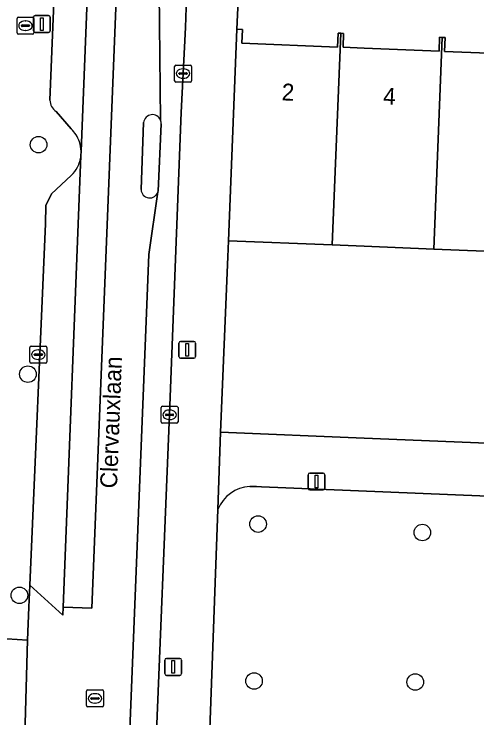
# Model space of a CAD drawing. Extents: x 160786 to 161429, y 386828 to 387485.
# Drawn here: x 160979.3 to 161006.66, y 386923.3 to 386964.94 of the extents above; entities that cross this region are included whole.
import ezdxf

# ---------------------------------------------------------------- set-up
doc = ezdxf.new("R2010")
doc.units = 0
for name, color, linetype in [('IMGEO_Boom', 7, 'Continuous'), ('IMGEO_Brandkraan', 7, 'Continuous'), ('IMGEO_Erf', 7, 'Continuous'), ('IMGEO_Groenvoorziening', 7, 'Continuous'), ('IMGEO_Kolk', 7, 'Continuous'), ('IMGEO_Lichtmast', 7, 'Continuous'), ('IMGEO_Muur', 7, 'Continuous'), ('IMGEO_Openbare_ruimte_label', 7, 'Continuous'), ('IMGEO_Pand', 7, 'Continuous'), ('IMGEO_Pand_nummerreeks', 7, 'Continuous'), ('IMGEO_Parkeervlak_gesloten', 7, 'Continuous'), ('IMGEO_Rijbaan_lokaal_gesloten', 7, 'Continuous'), ('IMGEO_Rijbaan_lokaal_open', 7, 'Continuous'), ('IMGEO_Rioolput', 7, 'Continuous'), ('IMGEO_Verkeerseiland_gesloten', 7, 'Continuous'), ('IMGEO_Voetpad_open', 7, 'Continuous')]:
    doc.layers.add(name, color=color, linetype=linetype)

msp = doc.modelspace()

# ---------------------------------------------------------------- linework, layer by layer
at = {"layer": 'IMGEO_Boom'}
for centre in [(160980.747, 386957.214), (160980.116, 386943.638), (160993.724, 386934.769), (161003.435, 386934.27), (160979.614, 386930.557), (160993.485, 386925.485), (161003.015, 386925.424)]:
    msp.add_circle(centre, 0.489, dxfattribs=at)
at = {"layer": 'IMGEO_Brandkraan'}
for p, q in [((160979.472, 386963.826), (160979.472, 386964.678)), ((160979.547, 386964.752), (160980.399, 386964.752)), ((160979.96, 386964.532), (160979.985, 386964.532)), ((160980.473, 386964.678), (160980.473, 386963.826)), ((160979.731, 386964.246), (160979.731, 386964.258)), ((160980.169, 386964.209), (160979.771, 386964.209)), ((160979.774, 386964.295), (160980.172, 386964.295)), ((160979.983, 386963.972), (160979.958, 386963.972)), ((160980.215, 386964.258), (160980.215, 386964.246)), ((160980.399, 386963.752), (160979.547, 386963.752))]:
    msp.add_line(p, q, dxfattribs=at)
for points in [[(160979.472, 386963.826), (160979.472, 386964.678)], [(160979.547, 386964.752), (160980.399, 386964.752)], [(160980.473, 386964.678), (160980.473, 386963.826)], [(160980.399, 386963.752), (160979.547, 386963.752)]]:
    msp.add_lwpolyline(points, dxfattribs=at)
for centre, radius, start, end in [((160979.549, 386964.676), 0.0765, 91.552, 178.448), ((160979.549, 386964.676), 0.0765, 91.552, 178.448), ((160980.397, 386964.676), 0.0765, 1.552, 88.448), ((160980.397, 386964.676), 0.0765, 1.552, 88.448), ((160979.771, 386964.255), 0.0403, 85.8775, 175.7526), ((160979.768, 386964.245), 0.0366, 178.938, 274.7102), ((160980.172, 386964.252), 0.043, 264.8664, 352.4533), ((160980.176, 386964.257), 0.0386, 1.7309, 96.639), ((160979.549, 386963.828), 0.0765, 181.552, 268.448), ((160979.549, 386963.828), 0.0765, 181.552, 268.448), ((160980.397, 386963.828), 0.0765, 271.552, 358.448), ((160980.397, 386963.828), 0.0765, 271.552, 358.448)]:
    msp.add_arc(centre, radius, start, end, dxfattribs=at)
for centre, major_axis, ratio, start_param, end_param in [((160979.959, 386964.252), (-0.387, 0.002), 0.722429, 4.712389, 7.853982), ((160979.984, 386964.252), (-0.39, 0.002), 0.717154, 1.570796, 4.712389)]:
    msp.add_ellipse(centre, major_axis=major_axis, ratio=ratio, start_param=start_param, end_param=end_param, dxfattribs=at)
at = {"layer": 'IMGEO_Erf'}
msp.add_lwpolyline([(161033.803, 386940.315), (161034.227, 386948.864), (161034.266, 386949.814), (161028.105, 386950.064), (161022.105, 386950.308), (161016.105, 386950.552), (161010.106, 386950.796), (161004.105, 386951.04), (161000, 386951.207), (160998.105, 386951.284), (160991.968, 386951.533), (160991.929, 386950.583), (160991.5, 386940.197), (161000, 386939.854), (161031.883, 386938.55)], dxfattribs=at)
at = {"layer": 'IMGEO_Groenvoorziening'}
for points in [[(161033.104, 386927.737), (161012.25, 386928.575), (161012.565, 386936.195), (160993.932, 386936.966), (160993.624, 386936.993), (160993.229, 386936.995)], [(160991.347, 386935.625), (160990.649, 386916.69)]]:
    msp.add_lwpolyline(points, dxfattribs=at)
msp.add_arc((160993.352, 386934.848), 2.151, 93.2892, 158.8162, dxfattribs=at)
at = {"layer": 'IMGEO_Kolk'}
for p, q in [((160988.864, 386961.92), (160989.716, 386961.92)), ((160988.789, 386960.994), (160988.789, 386961.846)), ((160989.091, 386961.463), (160989.489, 386961.463)), ((160989.277, 386961.7), (160989.302, 386961.7)), ((160989.79, 386961.846), (160989.79, 386960.994)), ((160989.048, 386961.414), (160989.048, 386961.426)), ((160989.486, 386961.377), (160989.088, 386961.377)), ((160989.3, 386961.14), (160989.275, 386961.14)), ((160989.532, 386961.426), (160989.532, 386961.414)), ((160989.716, 386960.92), (160988.864, 386960.92)), ((160980.234, 386944.365), (160980.234, 386945.217)), ((160980.309, 386945.291), (160981.161, 386945.291)), ((160981.235, 386945.217), (160981.235, 386944.365)), ((160980.493, 386944.785), (160980.493, 386944.797)), ((160980.536, 386944.834), (160980.934, 386944.834)), ((160980.722, 386945.071), (160980.747, 386945.071)), ((160980.977, 386944.797), (160980.977, 386944.785)), ((160980.931, 386944.748), (160980.533, 386944.748)), ((160980.745, 386944.511), (160980.72, 386944.511)), ((160981.161, 386944.291), (160980.309, 386944.291)), ((160987.99, 386940.81), (160987.99, 386941.662)), ((160988.065, 386941.736), (160988.917, 386941.736)), ((160988.478, 386941.516), (160988.503, 386941.516)), ((160988.991, 386941.662), (160988.991, 386940.81)), ((160988.249, 386941.23), (160988.249, 386941.242)), ((160988.687, 386941.193), (160988.289, 386941.193)), ((160988.292, 386941.279), (160988.69, 386941.279)), ((160988.733, 386941.242), (160988.733, 386941.23)), ((160988.917, 386940.736), (160988.065, 386940.736)), ((160988.501, 386940.956), (160988.476, 386940.956))]:
    msp.add_line(p, q, dxfattribs=at)
for points in [[(160988.864, 386961.92), (160989.716, 386961.92)], [(160988.789, 386960.994), (160988.789, 386961.846)], [(160989.79, 386961.846), (160989.79, 386960.994)], [(160989.716, 386960.92), (160988.864, 386960.92)], [(160980.234, 386944.365), (160980.234, 386945.217)], [(160980.309, 386945.291), (160981.161, 386945.291)], [(160981.235, 386945.217), (160981.235, 386944.365)], [(160981.161, 386944.291), (160980.309, 386944.291)], [(160987.99, 386940.81), (160987.99, 386941.662)], [(160988.065, 386941.736), (160988.917, 386941.736)], [(160988.991, 386941.662), (160988.991, 386940.81)], [(160988.917, 386940.736), (160988.065, 386940.736)]]:
    msp.add_lwpolyline(points, dxfattribs=at)
for centre, radius, start, end in [((160988.866, 386961.844), 0.0765, 91.552, 178.448), ((160988.866, 386961.844), 0.0765, 91.552, 178.448), ((160989.714, 386961.844), 0.0765, 1.552, 88.448), ((160989.714, 386961.844), 0.0765, 1.552, 88.448), ((160989.088, 386961.423), 0.0403, 85.8775, 175.7526), ((160989.493, 386961.425), 0.0386, 1.7309, 96.639), ((160989.085, 386961.413), 0.0366, 178.938, 274.7102), ((160989.489, 386961.42), 0.043, 264.8664, 352.4533), ((160988.866, 386960.996), 0.0765, 181.552, 268.448), ((160988.866, 386960.996), 0.0765, 181.552, 268.448), ((160989.714, 386960.996), 0.0765, 271.552, 358.448), ((160989.714, 386960.996), 0.0765, 271.552, 358.448), ((160980.311, 386945.215), 0.0765, 91.552, 178.448), ((160980.311, 386945.215), 0.0765, 91.552, 178.448), ((160981.159, 386945.215), 0.0765, 1.552, 88.448), ((160981.159, 386945.215), 0.0765, 1.552, 88.448), ((160980.533, 386944.794), 0.0403, 85.8775, 175.7526), ((160980.53, 386944.784), 0.0366, 178.938, 274.7102), ((160980.934, 386944.791), 0.043, 264.8664, 352.4533), ((160980.938, 386944.796), 0.0386, 1.7309, 96.639), ((160980.311, 386944.367), 0.0765, 181.552, 268.448), ((160980.311, 386944.367), 0.0765, 181.552, 268.448), ((160981.159, 386944.367), 0.0765, 271.552, 358.448), ((160981.159, 386944.367), 0.0765, 271.552, 358.448), ((160988.067, 386941.66), 0.0765, 91.552, 178.448), ((160988.067, 386941.66), 0.0765, 91.552, 178.448), ((160988.915, 386941.66), 0.0765, 1.552, 88.448), ((160988.915, 386941.66), 0.0765, 1.552, 88.448), ((160988.289, 386941.239), 0.0403, 85.8775, 175.7526), ((160988.286, 386941.229), 0.0366, 178.938, 274.7102), ((160988.69, 386941.236), 0.043, 264.8664, 352.4533), ((160988.694, 386941.241), 0.0386, 1.7309, 96.639), ((160988.067, 386940.812), 0.0765, 181.552, 268.448), ((160988.067, 386940.812), 0.0765, 181.552, 268.448), ((160988.915, 386940.812), 0.0765, 271.552, 358.448), ((160988.915, 386940.812), 0.0765, 271.552, 358.448)]:
    msp.add_arc(centre, radius, start, end, dxfattribs=at)
for centre, major_axis, ratio, start_param, end_param in [((160989.276, 386961.42), (-0.387, 0.002), 0.722429, 4.712389, 7.853982), ((160989.301, 386961.42), (-0.39, 0.002), 0.717154, 1.570796, 4.712389), ((160980.721, 386944.791), (-0.387, 0.002), 0.722429, 4.712389, 7.853982), ((160980.746, 386944.791), (-0.39, 0.002), 0.717154, 1.570796, 4.712389), ((160988.477, 386941.236), (-0.387, 0.002), 0.722429, 4.712389, 7.853982), ((160988.502, 386941.236), (-0.39, 0.002), 0.717154, 1.570796, 4.712389)]:
    msp.add_ellipse(centre, major_axis=major_axis, ratio=ratio, start_param=start_param, end_param=end_param, dxfattribs=at)
at = {"layer": 'IMGEO_Lichtmast'}
for p, q in [((160980.543, 386964.851), (160981.333, 386964.851)), ((160981.333, 386964.851), (160980.543, 386964.851)), ((160980.443, 386963.951), (160980.443, 386964.751)), ((160980.443, 386964.751), (160980.443, 386963.951)), ((160981.433, 386964.751), (160981.433, 386963.951)), ((160981.433, 386963.951), (160981.433, 386964.751)), ((160981.333, 386963.851), (160980.543, 386963.851)), ((160980.543, 386963.851), (160981.333, 386963.851)), ((160989.041, 386944.679), (160989.041, 386945.479)), ((160989.041, 386945.479), (160989.041, 386944.679)), ((160989.141, 386945.579), (160989.931, 386945.579)), ((160989.931, 386945.579), (160989.141, 386945.579)), ((160990.031, 386945.479), (160990.031, 386944.679)), ((160990.031, 386944.679), (160990.031, 386945.479)), ((160989.931, 386944.579), (160989.141, 386944.579)), ((160989.141, 386944.579), (160989.931, 386944.579)), ((160996.777, 386937.79), (160997.567, 386937.79)), ((160997.567, 386937.79), (160996.777, 386937.79)), ((160996.677, 386936.89), (160996.677, 386937.69)), ((160996.677, 386937.69), (160996.677, 386936.89)), ((160997.667, 386937.69), (160997.667, 386936.89)), ((160997.667, 386936.89), (160997.667, 386937.69)), ((160997.567, 386936.79), (160996.777, 386936.79)), ((160996.777, 386936.79), (160997.567, 386936.79)), ((160988.208, 386925.921), (160988.208, 386926.721)), ((160988.208, 386926.721), (160988.208, 386925.921)), ((160988.308, 386926.821), (160989.098, 386926.821)), ((160989.098, 386926.821), (160988.308, 386926.821)), ((160989.198, 386926.721), (160989.198, 386925.921)), ((160989.198, 386925.921), (160989.198, 386926.721)), ((160989.098, 386925.821), (160988.308, 386925.821)), ((160988.308, 386925.821), (160989.098, 386925.821))]:
    msp.add_line(p, q, dxfattribs=at)
for points in [[(160980.863, 386964.726), (160981.013, 386964.726), (160981.013, 386963.976), (160980.863, 386963.976), (160980.863, 386964.726)], [(160989.461, 386945.454), (160989.611, 386945.454), (160989.611, 386944.704), (160989.461, 386944.704), (160989.461, 386945.454)], [(160997.097, 386937.665), (160997.247, 386937.665), (160997.247, 386936.915), (160997.097, 386936.915), (160997.097, 386937.665)], [(160988.628, 386926.696), (160988.778, 386926.696), (160988.778, 386925.946), (160988.628, 386925.946), (160988.628, 386926.696)]]:
    msp.add_lwpolyline(points, dxfattribs=at)
for centre, start, end in [((160980.543, 386964.751), 90, 180), ((160980.543, 386964.751), 90, 180), ((160981.333, 386964.751), 0, 90), ((160981.333, 386964.751), 360, 90), ((160980.543, 386963.951), 180, 270), ((160980.543, 386963.951), 180, 270), ((160981.333, 386963.951), 270, 0), ((160981.333, 386963.951), 270, 0), ((160989.141, 386945.479), 90, 180), ((160989.141, 386945.479), 90, 180), ((160989.931, 386945.479), 0, 90), ((160989.931, 386945.479), 360, 90), ((160989.141, 386944.679), 180, 270), ((160989.141, 386944.679), 180, 270), ((160989.931, 386944.679), 270, 0), ((160989.931, 386944.679), 270, 0), ((160996.777, 386937.69), 90, 180), ((160996.777, 386937.69), 90, 180), ((160997.567, 386937.69), 0, 90), ((160997.567, 386937.69), 360, 90), ((160996.777, 386936.89), 180, 270), ((160996.777, 386936.89), 180, 270), ((160997.567, 386936.89), 270, 0), ((160997.567, 386936.89), 270, 0), ((160988.308, 386926.721), 90, 180), ((160988.308, 386926.721), 90, 180), ((160989.098, 386926.721), 0, 90), ((160989.098, 386926.721), 360, 90), ((160988.308, 386925.921), 180, 270), ((160988.308, 386925.921), 180, 270), ((160989.098, 386925.921), 270, 0), ((160989.098, 386925.921), 270, 0)]:
    msp.add_arc(centre, 0.1, start, end, dxfattribs=at)
at = {"layer": 'IMGEO_Muur'}
for points in [[(160991.968, 386951.533), (160991.929, 386950.583)], [(160991.929, 386950.583), (160991.5, 386940.197)]]:
    msp.add_lwpolyline(points, dxfattribs=at)
at = {"layer": 'IMGEO_Pand'}
for points in [[(160998.457, 386963.811), (160998.424, 386962.985), (160992.763, 386963.215), (160992.796, 386964.034), (160992.476, 386964.047), (160991.968, 386951.533), (160998.105, 386951.284), (160998.615, 386963.805)], [(161004.457, 386963.567), (161004.424, 386962.748), (161000, 386962.928), (160998.744, 386962.979), (160998.777, 386963.798), (160998.615, 386963.805), (160998.105, 386951.284), (161000, 386951.207), (161004.105, 386951.04), (161004.615, 386963.561)], [(161010.457, 386963.323), (161010.424, 386962.504), (161004.744, 386962.735), (161004.777, 386963.554), (161004.615, 386963.561), (161004.105, 386951.04), (161010.106, 386950.796), (161010.615, 386963.316)]]:
    msp.add_lwpolyline(points, close=True, dxfattribs=at)
at = {"layer": 'IMGEO_Parkeervlak_gesloten'}
for points in [[(160984.531, 386988.762), (160982.59, 386988.817), (160981.419, 386959.85)], [(160983.262, 386956.829), (160984.531, 386988.762)], [(160981.781, 386959.176), (160982.672, 386958.148)], [(160982.678, 386955.399), (160981.517, 386954.306), (160981.17, 386953.623), (160981.158, 386952.537), (160980.231, 386931.159), (160982.189, 386929.378), (160982.208, 386929.85), (160983.251, 386956.562)]]:
    msp.add_lwpolyline(points, dxfattribs=at)
for centre, radius, start, end in [((160982.252, 386959.863), 0.833, 180.8942, 235.5856), ((160981.348, 386956.761), 1.917, 18.7919, 46.3239), ((160981.383, 386956.775), 1.88, 1.6551, 18.7529), ((160981.365, 386956.769), 1.897, 332.3721, 353.7458), ((160981.371, 386956.764), 1.89, 313.7635, 332.4219)]:
    msp.add_arc(centre, radius, start, end, dxfattribs=at)
at = {"layer": 'IMGEO_Rijbaan_lokaal_gesloten'}
for points in [[(160987.959, 386958.658), (160987.876, 386966.266), (160992.785, 387087.527), (160990.199, 387087.638), (160983.902, 386929.785), (160982.208, 386929.85), (160982.189, 386929.378), (160980.231, 386931.159), (160980.175, 386929.863), (160980.09, 386927.898), (160979.942, 386922.265), (160979.941, 386922.229), (160981.745, 386922.17)], [(160984.712, 386993.626), (160984.531, 386988.762), (160983.262, 386956.829), (160983.251, 386956.562), (160982.208, 386929.85), (160983.902, 386929.785), (160990.199, 387087.638)], [(160992.274, 387030.665), (160992.337, 387032.289), (160992.597, 387038.997), (160993.259, 387056.065), (160994.21, 387079.435), (160994.515, 387085.035), (160994.612, 387087.501), (160992.785, 387087.527), (160987.876, 386966.266), (160987.959, 386958.658)], [(160987.64, 386919.555), (160987.637, 386920.517), (160988.491, 386941.272), (160989.174, 386959.126), (160989.425, 386964.144), (160989.53, 386967.133), (160989.72, 386972.632), (160989.974, 386978.34), (160990.002, 386979.005), (160990.152, 386982.628), (160990.167, 386982.998), (160990.497, 386990.405), (160990.992, 387000), (160991.155, 387003.893), (160991.434, 387010.584), (160992.274, 387030.665)], [(160987.992, 386958.443), (160987.814, 386954.469), (160987.805, 386954.433), (160987.273, 386950.712), (160986.053, 386920.644)], [(160986.805, 386954.556), (160986.957, 386958.522)], [(160986.053, 386920.644), (160987.273, 386950.712), (160987.805, 386954.433)]]:
    msp.add_lwpolyline(points, dxfattribs=at)
for centre, radius, start, end in [((160987.474, 386958.473), 0.519, 20.8346, 174.6243), ((160987.477, 386958.474), 0.516, 356.5558, 20.8965), ((160987.314, 386954.57), 0.509, 181.5273, 344.4484)]:
    msp.add_arc(centre, radius, start, end, dxfattribs=at)
at = {"layer": 'IMGEO_Rijbaan_lokaal_open'}
for points in [[(160992.599, 386967.047), (160992.476, 386964.047), (160992.796, 386964.034), (160992.763, 386963.215), (160998.424, 386962.985), (160998.457, 386963.811), (160998.615, 386963.805), (160998.777, 386963.798), (160998.744, 386962.979), (161000, 386962.928), (161004.424, 386962.748), (161004.457, 386963.567), (161004.615, 386963.561), (161004.777, 386963.554), (161004.744, 386962.735), (161010.424, 386962.504), (161010.457, 386963.323), (161010.615, 386963.316), (161010.776, 386963.309), (161010.743, 386962.49), (161016.203, 386962.268), (161016.581, 386971.618)], [(160950.247, 386936.098), (160950.494, 386941.959), (160947.593, 386942.07), (160909.763, 386943.521), (160909.024, 386925.361), (160908.899, 386922.288), (160924.183, 386921.716), (160939.56, 386921.141), (160942.121, 386921.036), (160965.405, 386920.165), (160967.922, 386920.071), (160968.031, 386922.765), (160970.467, 386922.647), (160978.3, 386922.336), (160979.942, 386922.265), (160980.09, 386927.898), (160977.011, 386928.093), (160956.943, 386928.854)]]:
    msp.add_lwpolyline(points, dxfattribs=at)
at = {"layer": 'IMGEO_Rioolput'}
for p, q in [((160983.578, 386924.031), (160983.578, 386924.883)), ((160983.653, 386924.957), (160984.505, 386924.957)), ((160984.579, 386924.883), (160984.579, 386924.031)), ((160983.837, 386924.451), (160983.837, 386924.463)), ((160984.275, 386924.414), (160983.877, 386924.414)), ((160983.88, 386924.5), (160984.278, 386924.5)), ((160984.066, 386924.737), (160984.091, 386924.737)), ((160984.321, 386924.463), (160984.321, 386924.451)), ((160984.089, 386924.177), (160984.064, 386924.177)), ((160984.505, 386923.957), (160983.653, 386923.957))]:
    msp.add_line(p, q, dxfattribs=at)
for points in [[(160983.578, 386924.031), (160983.578, 386924.883)], [(160983.653, 386924.957), (160984.505, 386924.957)], [(160984.579, 386924.883), (160984.579, 386924.031)], [(160984.505, 386923.957), (160983.653, 386923.957)]]:
    msp.add_lwpolyline(points, dxfattribs=at)
for centre, radius, start, end in [((160983.655, 386924.881), 0.0765, 91.552, 178.448), ((160983.655, 386924.881), 0.0765, 91.552, 178.448), ((160984.503, 386924.881), 0.0765, 1.552, 88.448), ((160984.503, 386924.881), 0.0765, 1.552, 88.448), ((160983.877, 386924.46), 0.0403, 85.8775, 175.7526), ((160983.874, 386924.45), 0.0366, 178.938, 274.7102), ((160984.278, 386924.457), 0.043, 264.8664, 352.4533), ((160984.282, 386924.462), 0.0386, 1.7309, 96.639), ((160983.655, 386924.033), 0.0765, 181.552, 268.448), ((160983.655, 386924.033), 0.0765, 181.552, 268.448), ((160984.503, 386924.033), 0.0765, 271.552, 358.448), ((160984.503, 386924.033), 0.0765, 271.552, 358.448)]:
    msp.add_arc(centre, radius, start, end, dxfattribs=at)
for centre, major_axis, ratio, start_param, end_param in [((160984.065, 386924.457), (-0.387, 0.002), 0.722429, 4.712389, 7.853982), ((160984.09, 386924.457), (-0.39, 0.002), 0.717154, 1.570796, 4.712389)]:
    msp.add_ellipse(centre, major_axis=major_axis, ratio=ratio, start_param=start_param, end_param=end_param, dxfattribs=at)
at = {"layer": 'IMGEO_Verkeerseiland_gesloten'}
for points in [[(160986.957, 386958.522), (160986.805, 386954.556)], [(160987.805, 386954.433), (160987.814, 386954.469), (160987.992, 386958.443)]]:
    msp.add_lwpolyline(points, dxfattribs=at)
for centre, radius, start, end in [((160987.474, 386958.473), 0.519, 20.8346, 174.6243), ((160987.477, 386958.474), 0.516, 356.5558, 20.8965), ((160987.314, 386954.57), 0.509, 181.5273, 344.4484)]:
    msp.add_arc(centre, radius, start, end, dxfattribs=at)
at = {"layer": 'IMGEO_Voetpad_open'}
for points in [[(160981.419, 386959.85), (160982.59, 386988.817), (160982.679, 386991.028), (160983.018, 386991.698), (160984.269, 386992.759)], [(160977.018, 386992.268), (160976.973, 386989.708), (160979.245, 386983.695), (160979.111, 386978.996), (160979.035, 386977.005), (160978.96, 386975.016), (160978.59, 386965.715), (160978.516, 386963.768), (160978.441, 386961.82), (160978.026, 386952.65), (160977.951, 386950.68), (160977.876, 386948.712), (160977.497, 386939.446), (160977.422, 386937.468), (160977.347, 386935.491), (160977.011, 386928.093), (160980.09, 386927.898), (160980.175, 386929.863), (160980.231, 386931.159), (160981.158, 386952.537), (160981.17, 386953.623), (160981.517, 386954.306), (160982.678, 386955.399)], [(160991.347, 386935.625), (160991.5, 386940.197), (160991.929, 386950.583), (160991.968, 386951.533), (160992.476, 386964.047), (160992.599, 386967.047), (160989.53, 386967.133), (160989.425, 386964.144), (160989.174, 386959.126), (160988.491, 386941.272), (160987.637, 386920.517), (160987.64, 386919.555)], [(160982.672, 386958.148), (160981.781, 386959.176)], [(160983.251, 386956.562), (160983.262, 386956.829)], [(161090.255, 386936.31), (161090.15, 386936.295), (161082.967, 386936.595), (161082.88, 386936.613), (161038.862, 386938.273), (161038.808, 386938.265), (161031.942, 386938.539), (161031.883, 386938.55), (161000, 386939.854), (160991.5, 386940.197), (160991.347, 386935.625)], [(160993.229, 386936.995), (160993.624, 386936.993), (160993.932, 386936.966), (161012.565, 386936.195), (161031.411, 386935.415), (161031.656, 386935.361), (161031.901, 386935.303), (161032.069, 386935.257), (161032.386, 386935.15)], [(160989.719, 386913.07), (160990.649, 386916.69), (160991.347, 386935.625)]]:
    msp.add_lwpolyline(points, dxfattribs=at)
for centre, radius, start, end in [((160982.252, 386959.863), 0.833, 180.8942, 235.5856), ((160981.348, 386956.761), 1.917, 18.7919, 46.3239), ((160981.383, 386956.775), 1.88, 1.6551, 18.7529), ((160981.365, 386956.769), 1.897, 332.3721, 353.7458), ((160981.371, 386956.764), 1.89, 313.7635, 332.4219), ((160993.352, 386934.848), 2.151, 93.2892, 158.8162)]:
    msp.add_arc(centre, radius, start, end, dxfattribs=at)

# ---------------------------------------------------------------- texts
at = {"layer": 'IMGEO_Openbare_ruimte_label'}
msp.add_text('Clervauxlaan', height=1, rotation=87.8216, dxfattribs=at).set_placement((160985.38, 386936.869))
at = {"layer": 'IMGEO_Pand_nummerreeks'}
for s, rotation, p in [('2', 357.6734, (160995.102, 386959.838)), ('4', 357.6796, (161001.099, 386959.595))]:
    msp.add_text(s, height=1, rotation=rotation, dxfattribs=at).set_placement(p)

doc.saveas('drawing.dxf')
